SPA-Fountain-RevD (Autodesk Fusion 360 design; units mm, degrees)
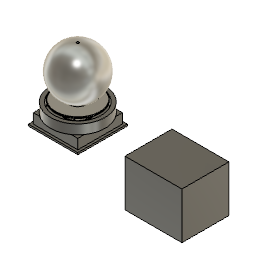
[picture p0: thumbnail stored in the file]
part number: 2026-08-05-01-10-42-045
part number: 2026-08-05-01-10-57-397
part number: 2026-08-05-01-11-41-392
part number: 2026-08-05-01-12-41-410
part number: 2026-08-05-01-12-42-788
part number: 2026-08-05-01-13-16-112
part number: 2026-08-05-01-13-16-264
part number: 2026-08-05-01-13-52-710
part number: 2026-08-05-01-13-53-458
part number: 2026-08-05-01-13-54-092
part number: 2026-08-05-01-15-47-773
parameter "R_OUT" = 1000 comment "CONTROLLING outer radius"
parameter "shell_t" = 5
parameter "doubler_t" = 8 comment "internal doubler"
parameter "doubler_r0" = 242
parameter "doubler_r1" = 358
parameter "skirt_mean_D" = 600
parameter "skirt_t" = 10
parameter "skirt_H" = 446
parameter "z_flange_top" = -400 comment "base flange top face"
parameter "flange_OD" = 940
parameter "flange_ID" = 500
parameter "flange_t" = 25
parameter "bolt_PCD" = 800 comment "6 off at 60 deg"
parameter "jack_PCD" = 700
parameter "lift_PCD" = 800
parameter "dowel_PCD" = 720
parameter "embed_OD" = 940
parameter "embed_ID" = 560
parameter "embed_t" = 20
parameter "z_embed_top" = -450
parameter "stud_hef" = 250
parameter "grout_t" = 25
parameter "riser_OD" = 88.9
parameter "riser_wall" = 3.05
parameter "hole_fit" = 90 comment "+1/-0"
parameter "bellows_boss" = 110
parameter "vent_z" = 450
parameter "weep_PCD" = 150
parameter "tray_r0" = 310
parameter "tray_r1" = 900
parameter "z_tray_top" = -10
parameter "cham_ID" = 1900
parameter "cham_wall" = 150
parameter "z_cham_roof" = -70
parameter "pad_L" = 1800
parameter "pad_t" = 400
parameter "z_pad_top" = -450
parameter "res_int_L" = 1800
parameter "res_int_W" = 1400
parameter "res_int_H" = 1380
parameter "res_wall" = 250
parameter "z_res_floor" = -1700
parameter "z_res_TWL" = -550
parameter "res_offset" = 4000 comment "<=4 m to collector"
sketch "shell_profile" plane through (0, 0, 0) normal (0, 1, 0) x axis (1, 0, 0)
  line L1 (0, -5) -> (0, 0)
  line L2 (0, -1995) -> (0, -2000)
  arc A1 centre (0, -1000) radius 1000 clockwise from (0, -2000) to (0, 0)
  arc A2 centre (0, -1000) radius 995 clockwise from (0, -1995) to (0, -5)
  dimension "d45" radius A1 = 1000 (= "R_OUT")
  dimension "d46" radius A2 = 995 (= "R_OUT - shell_t")
revolve "Revolve1" sketch "shell_profile" AlongAngle 360 bodies "shell_body"
work_plane "WorkPlane1" AlongDistance 2050
sketch "cut_crown" plane through (0, 0, 2050) normal (0, 0, 1) x axis (1, 0, 0)
  circle C1 centre (0, 0) radius 45
  dimension "d49" diameter C1 = 90 (= "hole_fit")
extrude "Extrude1" cut sketch "cut_crown" + "Sketch1" profile of S1:C1 blind -80
work_plane "WorkPlane2" AlongDistance -50
sketch "cut_bottom" plane through (0, 0, -50) normal (0, 0, 1) x axis (1, 0, 0)
  circle C1 centre (0, 0) radius 45
  circle C2 centre (75, 0) radius 5
  circle C3 centre (-75, 0) radius 5
  dimension "d53" diameter C1 = 90 (= "hole_fit")
extrude "Extrude2" cut sketch "cut_bottom" + "Sketch1" profile of S1:C1 S1:C2 S1:C3 blind 80
work_plane "WorkPlane3" AlongDistance -950
sketch "cut_vents" plane through (-950, 0, 0) normal (1, 0, 0) x axis (0, 0, -1)
  circle C1 centre (-450, 0) radius 5
extrude "Extrude3" cut sketch "cut_vents" + "Sketch1" profile of S1:C1 blind 1900
place_component sketch "Sketch1"
sketch "Sketch1" plane through (0, 0, 0) normal (0, 1, 0) x axis (1, 0, 0)
  line L1 (274, -51.7949) -> (242, -34.8777)
  line L2 (358, -71.6353) -> (326, -68.3922)
  arc A1 centre (0, -1000) radius 995 clockwise from (242, -34.8777) to (358, -71.6353)
  arc A2 centre (0, -1000) radius 987 clockwise from (274, -51.7949) to (326, -68.3922)
revolve "Revolve1" sketch "Sketch1" AlongAngle 360 bodies "doubler"
sketch "Sketch1" plane through (0, 0, 0) normal (0, 1, 0) x axis (1, 0, 0)
  line L1 (305, -47.6476) -> (305, 400)
  line L2 (295, 400) -> (295, -44.5027)
  line L3 (305, 400) -> (295, 400)
  arc A1 centre (0, -1000) radius 1000 clockwise from (295, -44.5027) to (305, -47.6476)
revolve "Revolve1" sketch "Sketch1" AlongAngle 360 bodies "skirt"
work_plane "WorkPlane1" AlongDistance -400
sketch "Sketch2" plane through (-400, 0, 0) normal (1, 0, 0) x axis (0, 0, -1)
  line L1 (415, 30) -> (415, -30)
  line L2 (375, 30) -> (415, 30)
  line L3 (375, -30) -> (375, 30)
  line L4 (415, -30) -> (375, -30)
extrude "Extrude1" cut sketch "Sketch2" + "Sketch1" profile of S1:L1 S1:L2 S1:L3 S1:L4 blind 800
circular_pattern "C-Pattern1" TotalAngle 360
work_plane "WorkPlane1" AlongDistance -400
sketch "Sketch1" plane through (0, 0, -400) normal (0, 0, 1) x axis (1, 0, 0)
  circle C1 centre (0, 0) radius 470
  circle C2 centre (0, 0) radius 250
extrude "Extrude1" new body sketch "Sketch1" against normal blind 25 bodies "base_flange"
sketch "Sketch2" plane through (0, 0, -400) normal (0, 0, 1) x axis (1, 0, 0)
  circle C1 centre (385, 0) radius 10
  circle C2 centre (415, 0) radius 10
  circle C3 centre (192.5, 333.4198) radius 10
  circle C4 centre (207.5, 359.4005) radius 10
  circle C5 centre (-192.5, 333.4198) radius 10
  circle C6 centre (-207.5, 359.4005) radius 10
  circle C7 centre (-385, 0) radius 10
  circle C8 centre (-415, 0) radius 10
  circle C9 centre (-192.5, -333.4198) radius 10
  circle C10 centre (-207.5, -359.4005) radius 10
  circle C11 centre (192.5, -333.4198) radius 10
  circle C12 centre (207.5, -359.4005) radius 10
  circle C13 centre (350, 0) radius 10
  circle C14 centre (-175, 303.1089) radius 10
  circle C15 centre (-175, -303.1089) radius 10
  circle C16 centre (346.4102, 200) radius 10
  circle C17 centre (-200, 346.4102) radius 10
  circle C18 centre (-346.4102, -200) radius 10
  circle C19 centre (200, -346.4102) radius 10
  circle C20 centre (360, 0) radius 8.25
  circle C21 centre (-360, 0) radius 8.25
  circle C22 centre (219.2031, 219.2031) radius 6
  circle C23 centre (-219.2031, 219.2031) radius 6
  circle C24 centre (-219.2031, -219.2031) radius 6
  circle C25 centre (219.2031, -219.2031) radius 6
extrude "Extrude2" cut sketch "Sketch2" + "Sketch1" profile of S1:C1 S2:L3 S1:C3 S1:C4 S1:C5 S1:C6 S1:C7 S1:C8 S1:C9 S1:C10 S1:C11 S1:C12 S1:C13 S1:C14 S1:C15 S1:C16 S1:C17 S1:C18 S1:C19 S1:C20 S1:C21 S1:C22 S1:C23 S1:C24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 blind -30
work_plane "WorkPlane1" AlongDistance -450
sketch "Sketch1" plane through (0, 0, -450) normal (0, 0, 1) x axis (1, 0, 0)
  circle C1 centre (0, 0) radius 470
  circle C2 centre (0, 0) radius 280
extrude "Extrude1" new body sketch "Sketch1" against normal blind 20 bodies "embed_ring"
work_plane "WorkPlane2" AlongDistance -359
sketch "Sketch2" plane through (0, 0, -359) normal (0, 0, 1) x axis (1, 0, 0)
  circle C1 centre (400, 0) radius 8
  circle C2 centre (200, 346.4102) radius 8
  circle C3 centre (-200, 346.4102) radius 8
  circle C4 centre (-400, 0) radius 8
  circle C5 centre (-200, -346.4102) radius 8
  circle C6 centre (200, -346.4102) radius 8
extrude "Extrude2" new body sketch "Sketch2" against normal blind 400 bodies "stud_M16x400", "stud_M16x400 (1)", "stud_M16x400 (2)", "stud_M16x400 (3)", "stud_M16x400 (4)", "stud_M16x400 (5)"
sketch "Sketch3" plane through (0, 0, -450) normal (0, 0, 1) x axis (1, 0, 0)
  circle C1 centre (360, 0) radius 8
  circle C2 centre (-360, 0) radius 8
extrude "Extrude3" new body sketch "Sketch3" along normal blind 160 bodies "guide_dowel", "guide_dowel (1)"
work_plane "WorkPlane1" AlongDistance 1999.14
sketch "Sketch1" plane through (0, 0, 1999.14) normal (0, 0, 1) x axis (1, 0, 0)
  circle C1 centre (0, 0) radius 44.45
  circle C2 centre (0, 0) radius 41.4
  dimension "d80" diameter C1 = 88.9 (= "riser_OD")
  dimension "d81" diameter C2 = 82.8 (= "riser_OD - 2 * riser_wall")
extrude "Extrude1" new body sketch "Sketch1" against normal blind 2398.1 bodies "riser_pipe"
work_plane "WorkPlane2" AlongDistance -120
sketch "Sketch2" plane through (0, 0, -120) normal (0, 0, 1) x axis (1, 0, 0)
  circle C1 centre (0, 0) radius 55
  circle C2 centre (0, 0) radius 46
extrude "Extrude2" new body sketch "Sketch2" along normal blind 120 bodies "bellows_boss"
work_plane "WorkPlane1" AlongDistance -450
sketch "Sketch1" plane through (0, 0, -450) normal (0, 0, 1) x axis (1, 0, 0)
  line L1 (900, -900) -> (-900, -900)
  line L2 (900, 900) -> (900, -900)
  line L3 (-900, 900) -> (900, 900)
  line L4 (-900, -900) -> (-900, 900)
extrude "Extrude1" new body sketch "Sketch1" against normal blind 400 bodies "RC_pad_1800x1800x400"
work_plane "WorkPlane2" AlongDistance -850
sketch "Sketch2" plane through (0, 0, -850) normal (0, 0, 1) x axis (1, 0, 0)
  line L1 (1000, -1000) -> (-1000, -1000)
  line L2 (1000, 1000) -> (1000, -1000)
  line L3 (-1000, 1000) -> (1000, 1000)
  line L4 (-1000, -1000) -> (-1000, 1000)
extrude "Extrude2" new body sketch "Sketch2" against normal blind 75 bodies "blinding_75"
work_plane "WorkPlane3" AlongDistance -450
sketch "Sketch3" plane through (0, 0, -450) normal (0, 0, 1) x axis (1, 0, 0)
  circle C1 centre (0, 0) radius 1100
  circle C2 centre (0, 0) radius 950
extrude "Extrude3" new body sketch "Sketch3" along normal blind 380 bodies "collector_chamber_wall"
work_plane "WorkPlane4" AlongDistance -450
sketch "Sketch4" plane through (0, 0, -450) normal (0, 0, 1) x axis (1, 0, 0)
  circle C1 centre (0, 0) radius 360
  circle C2 centre (0, 0) radius 330
work_plane "WorkPlane1" AlongDistance -10
sketch "Sketch1" plane through (0, 0, -10) normal (0, 0, 1) x axis (1, 0, 0)
  circle C1 centre (0, 0) radius 900
  circle C2 centre (0, 0) radius 310
extrude "Extrude1" new body sketch "Sketch1" against normal blind 12 bodies "pebble_tray_deck"
work_plane "WorkPlane2" AlongDistance 28
sketch "Sketch2" plane through (0, 0, 28) normal (0, 0, 1) x axis (1, 0, 0)
  circle C1 centre (0, 0) radius 900
  circle C2 centre (0, 0) radius 890
work_plane "WorkPlane3" AlongDistance 50
sketch "Sketch3" plane through (0, 0, 50) normal (0, 0, 1) x axis (1, 0, 0)
  circle C1 centre (0, 0) radius 330
  circle C2 centre (0, 0) radius 316.25
extrude "Extrude3" new body sketch "Sketch3" against normal blind 60 bodies "reveal_collar_4mm_gap"
work_plane "WorkPlane1" AlongDistance -70
sketch "Sketch1" plane through (0, 0, -70) normal (0, 0, 1) x axis (1, 0, 0)
  line L1 (5150, -950) -> (2850, -950)
  line L2 (5150, 950) -> (5150, -950)
  line L3 (2850, 950) -> (5150, 950)
  line L4 (2850, -950) -> (2850, 950)
extrude "Extrude1" new body sketch "Sketch1" against normal blind 1880 bodies "reservoir_shell_ext"
work_plane "WorkPlane2" AlongDistance -320
sketch "Sketch2" plane through (0, 0, -320) normal (0, 0, 1) x axis (1, 0, 0)
  line L1 (4900, -700) -> (3100, -700)
  line L2 (4900, 700) -> (4900, -700)
  line L3 (3100, 700) -> (4900, 700)
  line L4 (3100, -700) -> (3100, 700)
extrude "Extrude2" cut sketch "Sketch2" + "Sketch1" profile of S1:L1 S1:L2 S1:L3 S1:L4 blind -1380
sketch "Sketch3" plane through (0, 0, -400) normal (0, 0, 1) x axis (1, 0, 0)
  line L1 (415, 10) -> (385, 10)
  line L2 (415, -10) -> (415, 10)
  line L3 (385, -10) -> (415, -10)
  line L4 (385, 10) -> (385, -10)
  line L5 (198.8397, 364.4005) -> (183.8397, 338.4198)
  line L6 (216.1603, 354.4005) -> (198.8397, 364.4005)
  line L7 (201.1603, 328.4198) -> (216.1603, 354.4005)
  line L8 (183.8397, 338.4198) -> (201.1603, 328.4198)
  line L9 (-216.1603, 354.4005) -> (-201.1603, 328.4198)
  line L10 (-198.8397, 364.4005) -> (-216.1603, 354.4005)
  line L11 (-183.8397, 338.4198) -> (-198.8397, 364.4005)
  line L12 (-201.1603, 328.4198) -> (-183.8397, 338.4198)
  line L13 (-415, -10) -> (-385, -10)
  line L14 (-415, 10) -> (-415, -10)
  line L15 (-385, 10) -> (-415, 10)
  line L16 (-385, -10) -> (-385, 10)
  line L17 (-198.8397, -364.4005) -> (-183.8397, -338.4198)
  line L18 (-216.1603, -354.4005) -> (-198.8397, -364.4005)
  line L19 (-201.1603, -328.4198) -> (-216.1603, -354.4005)
  line L20 (-183.8397, -338.4198) -> (-201.1603, -328.4198)
  line L21 (216.1603, -354.4005) -> (201.1603, -328.4198)
  line L22 (198.8397, -364.4005) -> (216.1603, -354.4005)
  line L23 (183.8397, -338.4198) -> (198.8397, -364.4005)
  line L24 (201.1603, -328.4198) -> (183.8397, -338.4198)
  circle C1 centre (298.7788, 172.5) radius 40
  circle C2 centre (0, 345) radius 40
  circle C3 centre (-298.7788, 172.5) radius 40
  circle C4 centre (-298.7788, -172.5) radius 40
  circle C5 centre (0, -345) radius 40
  circle C6 centre (298.7788, -172.5) radius 40
extrude "Extrude3" cut sketch "Sketch3" + "Sketch1" profile of S1:L1 S1:L2 S1:L3 S1:L4 S1:L5 S1:L6 S1:L7 S1:L8 S1:L9 S1:L10 S1:L11 S1:L12 S1:L13 S1:L14 S1:L15 S1:L16 S1:L17 S1:L18 S1:L19 S1:L20 S1:L21 S1:L22 S1:L23 S1:L24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 blind -30
work_plane "WorkPlane1" AlongDistance -450
sketch "Sketch1" plane through (0, 0, -450) normal (0, 0, 1) x axis (1, 0, 0)
  circle C1 centre (298.7788, 172.5) radius 30
  circle C2 centre (0, 345) radius 30
  circle C3 centre (-298.7788, 172.5) radius 30
  circle C4 centre (-298.7788, -172.5) radius 30
  circle C5 centre (0, -345) radius 30
  circle C6 centre (298.7788, -172.5) radius 30
extrude "Extrude1" new body sketch "Sketch1" along normal blind 230 bodies "tray_support_post", "tray_support_post (1)", "tray_support_post (2)", "tray_support_post (3)", "tray_support_post (4)", "tray_support_post (5)"
work_plane "WorkPlane2" AlongDistance -220
sketch "Sketch2" plane through (0, 0, -220) normal (0, 0, 1) x axis (1, 0, 0)
  circle C1 centre (0, 0) radius 360
  circle C2 centre (0, 0) radius 330
extrude "Extrude2" new body sketch "Sketch2" along normal blind 30 bodies "tray_support_ring"
work_plane "WorkPlane4" AlongDistance 30
sketch "Sketch4" plane through (0, 0, 30) normal (0, 0, 1) x axis (1, 0, 0)
  circle C1 centre (0, 0) radius 900
  circle C2 centre (0, 0) radius 890
extrude "Extrude4" new body sketch "Sketch4" against normal blind 40 bodies "tray_upstand_outer"
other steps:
create_component "CreateComponent1"
create_component "CreateComponent2" sketch "Sketch1"
create_component "CreateComponent3"
create_component "CreateComponent4"
create_component "CreateComponent5"
create_component "CreateComponent6"
create_component "CreateComponent7"
create_component "CreateComponent8"
create_component "CreateComponent9"
create_component "CreateComponent10"
named bodies: "shell_body", "doubler", "skirt", "base_flange", "embed_ring", "stud_M16x400", "stud_M16x400 (1)", "stud_M16x400 (2)", "stud_M16x400 (3)", "stud_M16x400 (4)", "stud_M16x400 (5)", "guide_dowel", "guide_dowel (1)", "riser_pipe", "bellows_boss", "RC_pad_1800x1800x400", "blinding_75", "collector_chamber_wall", "pebble_tray_deck", "reveal_collar_4mm_gap", "reservoir_shell_ext", "tray_support_post", "tray_support_post (1)", "tray_support_post (2)", "tray_support_post (3)", "tray_support_post (4)", "tray_support_post (5)", "tray_support_ring", "tray_upstand_outer"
